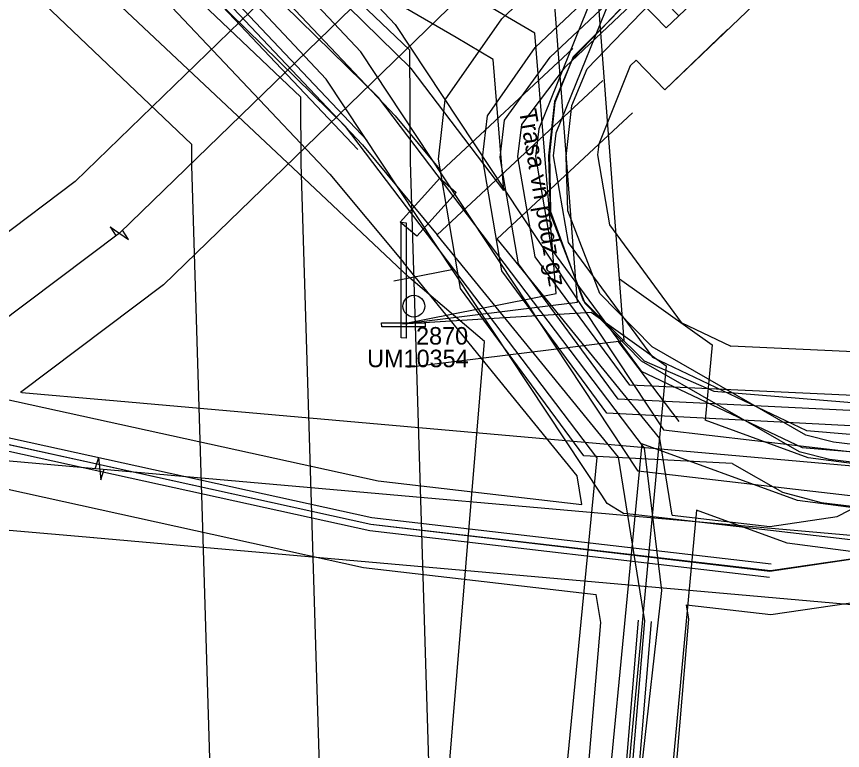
# Model space of a CAD drawing. Extents: x -762993 to -761845, y -975230 to -974501.
# Drawn here: x -762259.7 to -762240.82, y -975000.59 to -974983.83 of the extents above; entities that cross this region are included whole.
import ezdxf

# ---------------------------------------------------------------- set-up
doc = ezdxf.new("R2010")
doc.units = 0
for name, color, linetype in [('IS_CETIN_chranicka', 7, 'Continuous'), ('IS_CETIN_OP', 7, 'Continuous'), ('IS_CETIN_podzem metalika zam', 7, 'Continuous'), ('IS_CETIN_podzem optika zam', 7, 'Continuous'), ('IS_CETIN_podzem out of order', 7, 'Continuous'), ('IS_CEZ-D_anotace', 7, 'Continuous'), ('IS_CEZ-D_el vedeni NN podzem', 7, 'Continuous'), ('IS_CEZ-D_el vedeni VN podzem', 7, 'Continuous'), ('IS_CEZ-D_el vedeni VN podzem soubeh investice', 7, 'Continuous'), ('IS_CEZ-D_OP', 7, 'Continuous'), ('IS_CEZ-T_parovod', 7, 'Continuous'), ('IS_CEZ-T_parovod OP', 7, 'Continuous'), ('IS_CRA_podzem telekomunikace', 7, 'Continuous'), ('IS_DPmUL_OP', 7, 'Continuous'), ('IS_DPmUL_trakce anotace', 7, 'Continuous'), ('IS_DPmUL_trakce stozary', 7, 'Continuous'), ('IS_DPmUL_trakce vedeni', 7, 'Continuous'), ('IS_DPmUL_VO lampy', 7, 'Continuous'), ('IS_DPmUL_VO lampy anotace', 7, 'Continuous'), ('IS_DPmUL_VO vedeni podzem', 7, 'Continuous'), ('IS_GASNET_plyn NTL rad', 7, 'Continuous'), ('IS_GASNET_plyn OP', 7, 'Continuous'), ('IS_SCVK_vodovod OP', 7, 'Continuous'), ('IS_SCVK_vodovod privadec', 7, 'Continuous'), ('IS_SCVK_vodovod znaky', 7, 'Continuous'), ('IS_TPS_podzem metalika', 7, 'Continuous')]:
    doc.layers.add(name, color=color, linetype=linetype)

msp = doc.modelspace()

# ---------------------------------------------------------------- linework, layer by layer
at = {"layer": 'IS_CETIN_chranicka'}
for points in [[(-762258.261, -974979.697), (-762251.681, -974986.657)], [(-762258.479, -974979.903), (-762251.899, -974986.863)], [(-762286.819, -974981.848), (-762283.199, -974983.778), (-762274.07, -974988.662), (-762260.489, -974993.315), (-762251.575, -974995.272), (-762242.453, -974996.331)], [(-762286.961, -974982.112), (-762283.341, -974984.042), (-762274.19, -974988.938), (-762260.571, -974993.605), (-762251.625, -974995.568), (-762242.487, -974996.629)], [(-762245.489, -974997.617), (-762246.179, -975005.797)], [(-762245.191, -974997.643), (-762245.881, -975005.823)]]:
    msp.add_lwpolyline(points, dxfattribs=at)
at = {"layer": 'IS_CETIN_OP'}
for p, q in [((-762249.989, -974987.358), (-762246.981, -974984.558)), ((-762248.713, -974988.904), (-762245.619, -974986.022))]:
    msp.add_line(p, q, dxfattribs=at)
for points in [[(-762281.558, -974973.1), (-762274.643, -974973.209), (-762271.979, -974979.65), (-762261.259, -974982.679), (-762258.547, -974981.068), (-762252.538, -974987.424), (-762250.848, -974989.451)], [(-762257.358, -974979.415), (-762251.042, -974986.096), (-762249.989, -974987.358)], [(-762282.633, -974983.117), (-762273.729, -974987.88), (-762260.26, -974992.495), (-762251.435, -974994.432), (-762246.779, -974994.973)], [(-762283.324, -974985.015), (-762274.531, -974989.72), (-762260.8, -974994.425), (-762251.765, -974996.408), (-762246.45, -974997.025)], [(-762244.715, -974995.213), (-762244.995, -974993.466), (-762248.713, -974988.904)], [(-762246.779, -974994.973), (-762246.885, -974994.314), (-762250.855, -974989.442)], [(-762244.715, -974995.213), (-762242.485, -974995.472), (-762240.94, -974995.245), (-762237.434, -974993.44), (-762217.822, -974995.035)], [(-762244.386, -974997.264), (-762242.455, -974997.488), (-762240.32, -974997.175), (-762237.026, -974995.48), (-762217.984, -974997.029)], [(-762246.942, -975004.726), (-762246.347, -974997.668), (-762246.45, -974997.025)], [(-762244.95, -975004.903), (-762244.333, -974997.592), (-762244.386, -974997.264)]]:
    msp.add_lwpolyline(points, dxfattribs=at)
at = {"layer": 'IS_CETIN_podzem metalika zam'}
msp.add_lwpolyline([(-762250.08, -974988.81), (-762246.3, -974985.29)], dxfattribs=at)
at = {"layer": 'IS_CETIN_podzem optika zam'}
for points in [[(-762282.79, -974972.08), (-762273.97, -974972.22), (-762271.24, -974978.82), (-762261.4, -974981.6), (-762258.37, -974979.8), (-762251.79, -974986.76), (-762250.08, -974988.81)], [(-762274.13, -974988.8), (-762260.53, -974993.46), (-762251.6, -974995.42), (-762242.47, -974996.48), (-762240.63, -974996.21), (-762237.23, -974994.46), (-762217.903, -974996.032)], [(-762246.03, -975005.81), (-762245.34, -974997.63), (-762245.94, -974993.89), (-762250.08, -974988.81)]]:
    msp.add_lwpolyline(points, dxfattribs=at)
at = {"layer": 'IS_CETIN_podzem out of order'}
msp.add_lwpolyline([(-762250.2, -975005.66), (-762250.15, -975005.13), (-762249, -974991.25), (-762250.73, -974989.78), (-762252.74, -974987.88), (-762259.32, -974981.69), (-762267.11, -974979.9)], dxfattribs=at)
at = {"layer": 'IS_CEZ-D_el vedeni NN podzem'}
for points in [[(-762193.524, -974995.955), (-762196.315, -974995.713), (-762196.321, -974995.763), (-762206.82, -974995.223), (-762221.661, -974993.755), (-762245.947, -974992.564), (-762248.224, -974989.473), (-762248.642, -974987.043), (-762248.543, -974986.191), (-762247.498, -974984.757), (-762245.839, -974983.184), (-762245.485, -974982.848), (-762245.111, -974983.239), (-762244.564, -974983.81), (-762244.131, -974983.395)], [(-762193.524, -974995.955), (-762195.916, -974995.748), (-762195.968, -974996.181), (-762206.85, -974995.622), (-762221.698, -974994.154), (-762246.209, -974992.883), (-762248.603, -974989.634), (-762249.046, -974987.054), (-762248.934, -974986.091), (-762247.847, -974984.536), (-762246.114, -974982.893)], [(-762193.524, -974995.955), (-762196.714, -974995.678), (-762196.674, -974995.344), (-762206.79, -974994.824), (-762221.625, -974993.357), (-762245.684, -974992.246), (-762247.846, -974989.312), (-762248.238, -974987.032), (-762248.152, -974986.29), (-762247.149, -974984.977), (-762245.644, -974983.55), (-762245.499, -974983.413), (-762245.127, -974983.801), (-762244.853, -974984.087), (-762244.131, -974983.395)]]:
    msp.add_lwpolyline(points, dxfattribs=at)
at = {"layer": 'IS_CEZ-D_el vedeni VN podzem'}
for points in [[(-762269.579, -974969.967), (-762269.216, -974971.463), (-762268.263, -974975.531), (-762267.512, -974976.705), (-762264.757, -974978.053), (-762262.777, -974978.189), (-762259.951, -974977.791), (-762257.059, -974975.091), (-762254.069, -974975.768), (-762249.558, -974980.329), (-762249.105, -974980.676), (-762247.006, -974982.026), (-762245.904, -974982.859), (-762247.37, -974986.49), (-762247.43, -974987.01), (-762247.09, -974988.99), (-762245.16, -974991.61), (-762241.64, -974993.28), (-762221.77, -974994.95), (-762206.91, -974996.42), (-762195.262, -974997.018), (-762195.119, -974995.819), (-762194.458, -974994.436)], [(-762269.605, -974971.556), (-762268.637, -974975.689), (-762267.788, -974977.015), (-762264.863, -974978.447), (-762262.763, -974978.591), (-762259.77, -974978.169), (-762256.941, -974975.528), (-762254.271, -974976.132), (-762249.823, -974980.63), (-762249.335, -974981.004), (-762247.235, -974982.354), (-762246.39, -974982.993), (-762247.761, -974986.39), (-762247.834, -974987.021), (-762247.468, -974989.151), (-762245.422, -974991.928), (-762241.746, -974993.673), (-762221.806, -974995.348), (-762206.94, -974996.819), (-762194.909, -974997.437), (-762194.72, -974995.856), (-762194.458, -974994.436)], [(-762245.09, -974982.81), (-762246.99, -974984.79), (-762247.4, -974985.77), (-762247.54, -974987.01), (-762247.5, -974988.33), (-762246.71, -974990.37), (-762245.42, -974991.69), (-762241.81, -974993.76), (-762241.12, -974993.94), (-762236.96, -974994.44), (-762231.73, -974994.71), (-762227.11, -974994.8), (-762224.15, -974995.55), (-762219.32, -974995.76), (-762207.1, -974996.91), (-762200.67, -974997.34), (-762199.56, -974997.3), (-762198.56, -974996.73), (-762198.04, -974995.71)]]:
    msp.add_lwpolyline(points, dxfattribs=at)
at = {"layer": 'IS_CEZ-D_el vedeni VN podzem soubeh investice'}
msp.add_lwpolyline([(-762198.314, -974995.373), (-762198.862, -974996.442), (-762199.673, -974996.904), (-762200.675, -974996.938), (-762207.068, -974996.511), (-762219.294, -974995.361), (-762224.092, -974995.152), (-762227.056, -974994.401), (-762231.716, -974994.31), (-762236.926, -974994.041), (-762241.03, -974993.548), (-762241.657, -974993.386), (-762245.172, -974991.371), (-762246.367, -974990.149), (-762247.098, -974988.261), (-762247.139, -974987.026), (-762247.003, -974985.858), (-762246.655, -974985.018), (-762244.801, -974983.086)], dxfattribs=at)
at = {"layer": 'IS_CEZ-D_OP'}
msp.add_line((-762244.883, -974985.501), (-762243.439, -974984.117), dxfattribs=at)
for points in [[(-762242.822, -974981.871), (-762241.995, -974982.733), (-762244.883, -974985.501)], [(-762243.344, -974994.033), (-762246.733, -974993.857), (-762249.549, -974990.037), (-762250.056, -974987.081), (-762249.898, -974985.725), (-762248.609, -974983.88), (-762247.842, -974983.153)], [(-762245.671, -974984.954), (-762246.392, -974986.739), (-762246.42, -974986.982), (-762246.144, -974988.587), (-762244.504, -974990.814), (-762243.371, -974991.352)], [(-762245.671, -974984.954), (-762245.533, -974984.823), (-762244.883, -974985.501)], [(-762193.437, -974994.959), (-762195.598, -974994.771), (-762195.554, -974994.4), (-762206.715, -974993.827), (-762221.553, -974992.359), (-762243.371, -974991.352)], [(-762243.344, -974994.033), (-762242.192, -974994.694), (-762241.307, -974994.925), (-762237.046, -974995.437), (-762231.766, -974995.709), (-762227.244, -974995.798), (-762224.296, -974996.545), (-762219.389, -974996.758), (-762212.592, -974997.398)]]:
    msp.add_lwpolyline(points, dxfattribs=at)
at = {"layer": 'IS_CEZ-T_parovod'}
msp.add_lwpolyline([(-762252.5, -975008.59), (-762252.58, -975007.19), (-762253.19, -974987.18), (-762253.2, -974985.67), (-762257.54, -974981.54), (-762246.7, -974971.01), (-762237.24, -974961.81), (-762238.76, -974960.21), (-762237.06, -974958.42), (-762235.35, -974960.05), (-762220.52, -974945.72), (-762219.73, -974944.77), (-762200.92, -974926.55), (-762198.18, -974929.41), (-762193.38, -974924.68)], dxfattribs=at)
at = {"layer": 'IS_CEZ-T_parovod OP'}
for points in [[(-762254.996, -975008.733), (-762255.078, -975007.299), (-762255.69, -974987.226), (-762255.693, -974986.749), (-762261.147, -974981.559), (-762248.442, -974969.217), (-762240.754, -974961.74), (-762242.208, -974960.21), (-762237.148, -974954.882), (-762235.362, -974956.585), (-762222.355, -974944.017), (-762221.566, -974943.068), (-762200.854, -974923.005), (-762198.129, -974925.85), (-762195.116, -974922.881)], [(-762250.004, -975008.447), (-762250.082, -975007.081), (-762250.69, -974987.134), (-762250.707, -974984.591), (-762253.933, -974981.521), (-762244.958, -974972.803), (-762235.373, -974963.482), (-762235.338, -974963.515), (-762218.685, -974947.423), (-762217.894, -974946.472), (-762200.986, -974930.095), (-762198.231, -974932.97), (-762193.371, -974928.181)]]:
    msp.add_lwpolyline(points, dxfattribs=at)
at = {"layer": 'IS_CRA_podzem telekomunikace'}
for points in [[(-762276.159, -974987.718), (-762274.141, -974988.802), (-762260.544, -974993.454), (-762257.583, -974994.102)], [(-762257.583, -974994.102), (-762251.601, -974995.42), (-762242.483, -974996.496), (-762240.634, -974996.224), (-762237.225, -974994.464), (-762216.085, -974996.188), (-762184.646, -974998.998), (-762178.626, -974999.438), (-762152.565, -975001.658), (-762131.295, -975003.618), (-762124.896, -975004.158), (-762119.016, -975004.628), (-762113.267, -975005.088), (-762107.455, -975005.508), (-762100.504, -975006.198), (-762086.855, -975007.364)]]:
    msp.add_lwpolyline(points, dxfattribs=at)
at = {"layer": 'IS_DPmUL_OP'}
for p, q in [((-762251.073, -974989.864), (-762249.707, -974989.594)), ((-762244.551, -974993.078), (-762245.944, -974991.243))]:
    msp.add_line(p, q, dxfattribs=at)
for points in [[(-762250.756, -974991.837), (-762245.807, -974991.227), (-762246.542, -974981.579), (-762243.48, -974978.663)], [(-762246.438, -974993.901), (-762252.18, -974986.336), (-762258.617, -974980.029), (-762258.624, -974980.021)], [(-762248.56, -974987.797), (-762250.676, -974985.01), (-762253.935, -974981.816)], [(-762248.56, -974987.797), (-762248.807, -974984.805), (-762249.646, -974984.306), (-762253.935, -974981.816)], [(-762245.915, -974989.816), (-762243.803, -974991.324), (-762243.963, -974993.046)], [(-762222.768, -974996.366), (-762241.607, -974993.905), (-762243.963, -974993.046)], [(-762246.438, -974993.901), (-762247.521, -975005.081), (-762256.705, -975004.005)], [(-762244.155, -974995.105), (-762245.724, -975011.962), (-762246.319, -975011.976)], [(-762223.004, -974998.353), (-762242.085, -974995.859), (-762244.155, -974995.105)]]:
    msp.add_lwpolyline(points, dxfattribs=at)
at = {"layer": 'IS_DPmUL_trakce stozary'}
msp.add_circle((-762250.618, -974990.443), 0.25, dxfattribs=at)
at = {"layer": 'IS_DPmUL_trakce vedeni'}
for p, q in [((-762244.948, -974996.933), (-762245.348, -974993.683)), ((-762245.878, -975005.053), (-762244.948, -974996.933))]:
    msp.add_line(p, q, dxfattribs=at)
msp.add_lwpolyline([(-762245.348, -974993.683), (-762251.428, -974985.673), (-762257.908, -974979.323), (-762259.308, -974977.883), (-762264.868, -974978.223), (-762267.558, -974978.313), (-762268.458, -974976.203), (-762270.168, -974970.153), (-762271.628, -974963.603), (-762274.118, -974952.573), (-762276.178, -974943.173), (-762279.078, -974930.913), (-762281.258, -974920.463), (-762282.448, -974915.363), (-762282.938, -974913.343), (-762283.168, -974912.233), (-762284.728, -974904.823), (-762285.898, -974900.343), (-762287.198, -974894.413), (-762288.448, -974888.003), (-762289.278, -974884.593), (-762294.708, -974861.303), (-762294.911, -974860.32)], dxfattribs=at)
at = {"layer": 'IS_DPmUL_VO lampy'}
for points in [[(-762250.019, -974987.515), (-762249.649, -974987.845), (-762250.549, -974988.845), (-762250.929, -974988.525)], [(-762250.909, -974988.525), (-762250.789, -974988.535), (-762250.789, -974991.175), (-762250.909, -974991.165)], [(-762251.359, -974990.825), (-762250.359, -974990.825), (-762250.359, -974990.915), (-762251.349, -974990.915)]]:
    msp.add_lwpolyline(points, close=True, dxfattribs=at)
at = {"layer": 'IS_DPmUL_VO vedeni podzem'}
for points in [[(-762250.879, -974990.845), (-762246.877, -974990.351), (-762247.575, -974981.182), (-762244.17, -974977.939)], [(-762250.879, -974990.845), (-762247.363, -974990.15), (-762247.853, -974984.209), (-762249.139, -974983.444), (-762257.897, -974978.36), (-762260.929, -974980.32), (-762264.695, -974981.086), (-762267.897, -974979.732)], [(-762250.879, -974990.845), (-762246.567, -974990.579), (-762244.852, -974991.804), (-762246.637, -975010.983), (-762248.64, -975011.03)], [(-762222.898, -974997.358), (-762241.846, -974994.882), (-762245.403, -974993.586), (-762246.542, -975005.345), (-762246.899, -975006.161), (-762256.821, -975004.998)]]:
    msp.add_lwpolyline(points, dxfattribs=at)
at = {"layer": 'IS_GASNET_plyn NTL rad'}
msp.add_lwpolyline([(-762235.16, -974995.41), (-762241.303, -974994.697), (-762241.895, -974994.628), (-762245.49, -974994.21), (-762251.83, -974984.63), (-762254.68, -974981.6), (-762255.58, -974980.65), (-762257.13, -974979.62), (-762258.52, -974978.68), (-762260.62, -974979.38), (-762261.995, -974979.661), (-762262.553, -974979.775), (-762262.92, -974979.85), (-762265.56, -974979.89), (-762268.53, -974977.47), (-762279.25, -974979.81)], dxfattribs=at)
at = {"layer": 'IS_GASNET_plyn OP'}
msp.add_lwpolyline([(-762253.953, -974980.914), (-762251.043, -974984.007), (-762244.913, -974993.27), (-762241.779, -974993.635), (-762241.187, -974993.704), (-762235.045, -974994.417), (-762234.633, -974994.465), (-762234.119, -974995.114), (-762234.167, -974995.525), (-762234.215, -974995.937), (-762234.864, -974996.451), (-762235.275, -974996.403), (-762241.419, -974995.69), (-762242.011, -974995.621), (-762245.605, -974995.203), (-762245.825, -974995.178), (-762246.202, -974994.947), (-762246.324, -974994.762), (-762252.617, -974985.253), (-762255.407, -974982.286)], dxfattribs=at)
at = {"layer": 'IS_SCVK_vodovod OP'}
for p, q in [((-762258.353, -974987.594), (-762262.542, -974990.741)), ((-762256.335, -974989.956), (-762259.605, -974992.412))]:
    msp.add_line(p, q, dxfattribs=at)
for points in [[(-762217.473, -974947.113), (-762218.81, -974948.43), (-762220.343, -974950.02), (-762232.223, -974961.467), (-762242.519, -974972.237), (-762258.353, -974987.594)], [(-762215.297, -974949.321), (-762216.606, -974950.61), (-762218.151, -974952.212), (-762230.027, -974963.655), (-762240.319, -974974.421), (-762256.335, -974989.956)], [(-762259.587, -974992.399), (-762259.572, -974992.415), (-762257.661, -974992.58)], [(-762257.658, -974992.58), (-762207.497, -974997.012), (-762202.898, -974997.152)], [(-762261.984, -974994.467), (-762261.014, -974995.461), (-762257.933, -974995.728)], [(-762257.936, -974995.728), (-762207.685, -975000.168), (-762204.349, -975000.269)]]:
    msp.add_lwpolyline(points, dxfattribs=at)
at = {"layer": 'IS_SCVK_vodovod privadec'}
for points in [[(-762216.385, -974948.217), (-762217.708, -974949.52), (-762219.247, -974951.116), (-762231.125, -974962.561), (-762241.419, -974973.329), (-762257.344, -974988.775)], [(-762257.344, -974988.775), (-762261.568, -974991.948)], [(-762261.712, -974992.482), (-762260.293, -974993.938), (-762257.797, -974994.154)], [(-762257.797, -974994.154), (-762207.591, -974998.59), (-762203.041, -974998.728)]]:
    msp.add_lwpolyline(points, dxfattribs=at)
at = {"layer": 'IS_SCVK_vodovod znaky'}
for points in [[(-762257.553, -974988.63), (-762257.135, -974988.92)], [(-762257.553, -974988.63), (-762257.416, -974988.845)], [(-762257.135, -974988.92), (-762257.272, -974988.705)], [(-762257.824, -974993.9), (-762257.897, -974994.145)], [(-762257.824, -974993.9), (-762257.77, -974994.407)], [(-762257.77, -974994.407), (-762257.697, -974994.163)]]:
    msp.add_lwpolyline(points, dxfattribs=at)
at = {"layer": 'IS_TPS_podzem metalika'}
msp.add_lwpolyline([(-762240.486, -974977.956), (-762246.238, -974984.004), (-762246.978, -974984.75), (-762247.396, -974985.793), (-762247.518, -974986.973), (-762247.497, -974988.28), (-762246.746, -974990.312), (-762245.354, -974991.693), (-762243.76, -974992.38), (-762227.7, -974993.7), (-762194.072, -974996.484), (-762193.869, -974994.354), (-762196.707, -974994.049), (-762196.809, -974992.782), (-762196.146, -974992.699), (-762192.513, -974992.502)], dxfattribs=at)

# ---------------------------------------------------------------- texts
at = {"layer": 'IS_CEZ-D_anotace'}
msp.add_text('Trasa vn podz gz', height=0.4, rotation=279.7436, dxfattribs=at).set_placement((-762248.216, -974985.975))
at = {"layer": 'IS_DPmUL_trakce anotace'}
msp.add_text('2870', height=0.4, dxfattribs=at).set_placement((-762250.566, -974991.319))
at = {"layer": 'IS_DPmUL_VO lampy anotace'}
msp.add_text('UM10354', height=0.4, dxfattribs=at).set_placement((-762251.684, -974991.836))

doc.saveas('drawing.dxf')
